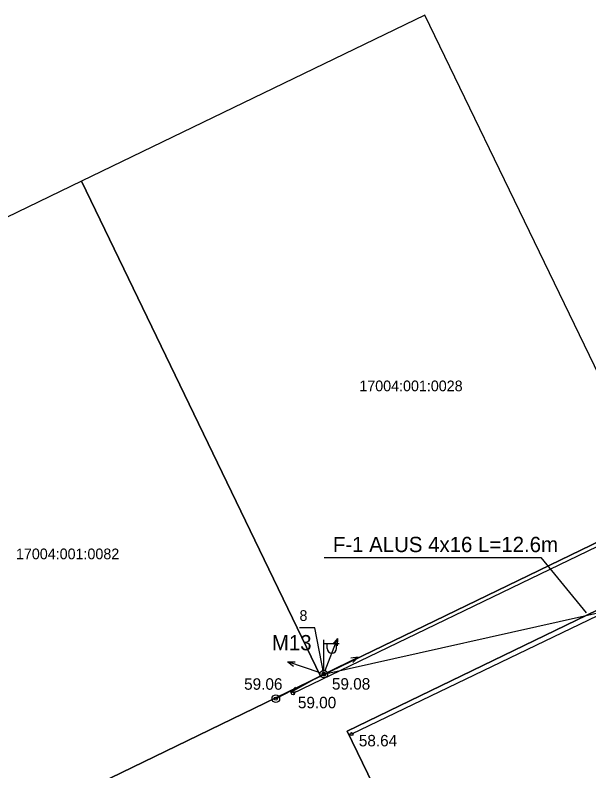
# Model space of a CAD drawing. Extents: x 643307 to 644029, y 6457938 to 6458417.
# Drawn here: x 643751.61 to 643789.21, y 6458367.55 to 6458417.04 of the extents above; entities that cross this region are included whole.
import ezdxf

# ---------------------------------------------------------------- set-up
doc = ezdxf.new("R2010")
doc.units = 0
for name, color, linetype in [('11_KTRASS', 7, 'Continuous'), ('14_MPOHULIIN', 7, 'Continuous'), ('26_POST', 7, 'Continuous'), ('28_AED', 7, 'Continuous'), ('40_PIIR', 7, 'Continuous'), ('59_KORGUS', 7, 'Continuous'), ('62_MOOTMPUNKT', 7, 'Continuous'), ('Level 25', 7, 'Continuous'), ('Level 55', 7, 'Continuous')]:
    doc.layers.add(name, color=color, linetype=linetype)

# ---------------------------------------------------------------- blocks, each defined once
blk = doc.blocks.new('RING02')
at = {"layer": '59_KORGUS'}
blk.add_circle((0, 0), 0.2, dxfattribs=at)
blk = doc.blocks.new('VAPOST')
at = {"layer": '11_KTRASS'}
for p, q in [((0, 0.5), (0, 4.5)), ((0, 4), (2, 4)), ((0.453, 3.358), (0.453, 4)), ((1.679, 3.358), (1.679, 4)), ((0, 0), (0, 0))]:
    blk.add_line(p, q, dxfattribs=at)
for radius in [0.5, 0.254]:
    blk.add_circle((0, 0), radius, dxfattribs=at)
blk.add_arc((1.066, 3.358), 0.613, 180, 0, dxfattribs=at)
blk = doc.blocks.new('TUPOST')
at = {"layer": '11_KTRASS'}
blk.add_circle((0, 0), 0.5, dxfattribs=at)
blk = doc.blocks.new('MPSUUN')
at = {"layer": '14_MPOHULIIN'}
for p, q in [((0, 0), (0, 0)), ((0.5, 0), (5, 0)), ((5, 0), (4.097, -0.297)), ((5, 0), (4.098, 0.3))]:
    blk.add_line(p, q, dxfattribs=at)

msp = doc.modelspace()

# ---------------------------------------------------------------- linework, layer by layer
at = {"layer": '14_MPOHULIIN'}
msp.add_line((643771.838, 6458373.892), (643797.493, 6458379.618), dxfattribs=at)
at = {"layer": '26_POST'}
msp.add_line((643768.692, 6458372.285), (643771.838, 6458373.892), dxfattribs=at)
at = {"layer": '28_AED'}
msp.add_line((643769.82, 6458372.633), (643794.208, 6458384.402), dxfattribs=at)
msp.add_lwpolyline([(643798.732, 6458378.182), (643797.225, 6458381.285), (643773.654, 6458369.962)], dxfattribs=at)
at = {"layer": '40_PIIR'}
for points in [[(643778.45, 6458417.04), (643755.95, 6458406.16), (643771.63, 6458373.76), (643794.13, 6458384.65)], [(643755.95, 6458406.16), (643733.44, 6458395.27), (643749.13, 6458362.87), (643771.63, 6458373.76)], [(643773.37, 6458370.16), (643795.88, 6458381.05), (643794.13, 6458384.65), (643771.63, 6458373.76), (643749.13, 6458362.87), (643764.81, 6458330.47), (643787.31, 6458341.36), (643783.83, 6458348.56)], [(643773.37, 6458370.16), (643783.83, 6458348.56), (643806.33, 6458359.45), (643795.88, 6458381.05)]]:
    msp.add_lwpolyline(points, close=True, dxfattribs=at)
at = {"layer": 'Level 25'}
for points in [[(643771.868, 6458381.534), (643786.057, 6458381.534), (643789.038, 6458377.914)], [(643771.838, 6458373.892), (643771.243, 6458376.926), (643770.243, 6458376.926)]]:
    msp.add_lwpolyline(points, dxfattribs=at)
at = {"layer": 'Level 55'}
for p, q in [((643771.838, 6458373.892), (643771.838, 6458373.892)), ((643769.82, 6458372.633), (643769.82, 6458372.633)), ((643768.692, 6458372.285), (643768.692, 6458372.285)), ((643773.654, 6458369.962), (643773.654, 6458369.962))]:
    msp.add_line(p, q, dxfattribs=at)

# ---------------------------------------------------------------- block references
at = {"layer": '14_MPOHULIIN'}
for xscale, yscale, rotation in [(0.5, 0.5000000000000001, 68.94645865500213), (0.49999999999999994, 0.5, 161.04364267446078), (0.49999999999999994, 0.5000000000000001, 26.158280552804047), (0.5, 0.5, -151.17854368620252)]:
    msp.add_blockref('MPSUUN', (643771.838, 6458373.892), dxfattribs=dict(at, xscale=xscale, yscale=yscale, rotation=rotation))
at = {"layer": '26_POST', "xscale": 0.5, "yscale": 0.5}
for name, p in [('VAPOST', (643771.838, 6458373.892)), ('TUPOST', (643768.692, 6458372.285))]:
    msp.add_blockref(name, p, dxfattribs=at)
at = {"layer": '62_MOOTMPUNKT', "xscale": 0.5, "yscale": 0.5}
for p in [(643771.838, 6458373.892), (643768.692, 6458372.285), (643769.82, 6458372.633), (643773.654, 6458369.962)]:
    msp.add_blockref('RING02', p, dxfattribs=at)

# ---------------------------------------------------------------- texts
at = {"layer": '40_PIIR'}
for s, p in [('17004:001:0028', (643774.164, 6458392.412)), ('17004:001:0082', (643751.664, 6458381.412))]:
    msp.add_text(s, height=0.7, dxfattribs=at).set_placement(p)
at = {"layer": '59_KORGUS'}
for s, p in [('59.06', (643766.615, 6458372.868)), ('59.08', (643772.369, 6458372.877)), ('59.00', (643770.139, 6458371.654)), ('58.64', (643774.132, 6458369.16))]:
    msp.add_text(s, height=0.75, dxfattribs=at).set_placement(p)
at = {"layer": 'Level 25'}
for s, height, p in [('F-1 ALUS 4x16 L=12.6m', 1, (643772.429, 6458381.879)), ('8', 0.7, (643770.243, 6458377.376)), ('M13', 1, (643768.433, 6458375.45))]:
    msp.add_text(s, height=height, dxfattribs=at).set_placement(p)

doc.saveas('drawing.dxf')
